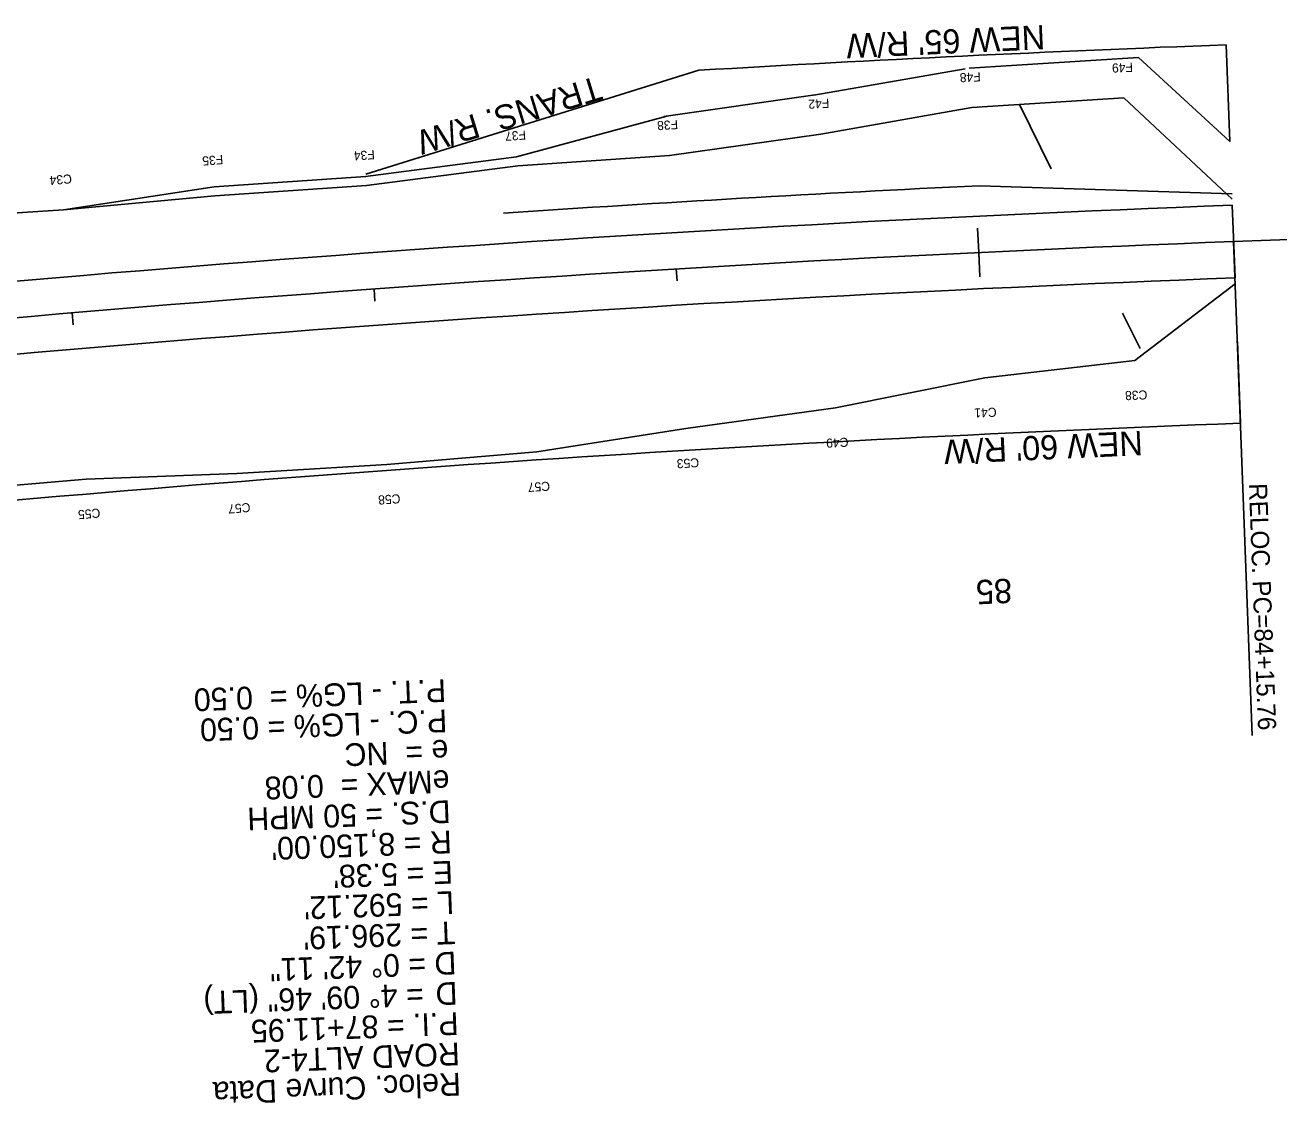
# Model space of a CAD drawing. Extents: x 1475170 to 1480100, y 1103245 to 1119475.
# Drawn here: x 1478026.2 to 1478440.1, y 1111115.9 to 1111471.6 of the extents above; entities that cross this region are included whole.
import ezdxf

# ---------------------------------------------------------------- set-up
doc = ezdxf.new("R2010")
doc.units = 0
for name, color, linetype in [('RD_HC_CL_Rel', 7, 'Continuous'), ('RD_HC_Data_Rel', 7, 'Continuous'), ('RD_HC_Data_Tic_Rel', 7, 'Continuous'), ('RD_HC_TX_Rel_Sta50', 7, 'Continuous'), ('RD_PD_CstnLmt', 7, 'Continuous'), ('RD_PD_CstnLmt_TX', 7, 'Continuous'), ('RD_PD_DR_ErosCtrl', 7, 'Continuous'), ('RD_PD_DR_Pipe', 7, 'Continuous'), ('RD_PD_Final_TrvlWay', 7, 'Continuous'), ('RD_PD_GR', 7, 'Continuous'), ('RD_PD_RW', 7, 'Continuous'), ('RD_PD_RW_TX', 7, 'Continuous')]:
    doc.layers.add(name, color=color, linetype=linetype)

msp = doc.modelspace()

# ---------------------------------------------------------------- linework, layer by layer
at = {"layer": 'RD_HC_CL_Rel'}
msp.add_line((1478857.19, 1111416.47), (1478425.19, 1111400.18), dxfattribs=at)
msp.add_arc((1478732.36, 1103255.97), 8150, 92.160003, 96.322689, dxfattribs=at)
at = {"layer": 'RD_HC_Data_Rel'}
msp.add_line((1478425.19, 1111400.18), (1478431.34, 1111237.13), dxfattribs=at)
at = {"layer": 'RD_HC_Data_Tic_Rel'}
for p, q in [((1478341.03, 1111396.57), (1478340.65, 1111404.56)), ((1478341.03, 1111396.57), (1478341.41, 1111388.58)), ((1478241.18, 1111391.15), (1478241.42, 1111387.16)), ((1478141.4, 1111384.51), (1478141.69, 1111380.52)), ((1478041.71, 1111376.65), (1478042.05, 1111372.67))]:
    msp.add_line(p, q, dxfattribs=at)
at = {"layer": 'RD_PD_CstnLmt'}
for p, q in [((1478338.73, 1111444.41), (1478288.84, 1111435.67)), ((1478288.84, 1111435.67), (1478238.91, 1111428.63)), ((1478238.91, 1111428.63), (1478188.8, 1111425.15)), ((1478188.8, 1111425.15), (1478138.91, 1111418.67)), ((1478088.82, 1111415.27), (1478038.82, 1111410.65)), ((1478138.91, 1111418.67), (1478088.82, 1111415.27)), ((1478038.82, 1111410.65), (1477988.68, 1111407.51)), ((1478343.02, 1111355.23), (1478293.74, 1111345.27)), ((1478293.74, 1111345.27), (1478244.36, 1111338.5)), ((1478244.36, 1111338.5), (1478195.09, 1111330.72)), ((1478195.09, 1111330.72), (1478145.61, 1111326.55)), ((1478145.61, 1111326.55), (1478096.04, 1111323.64)), ((1478046.37, 1111321.78), (1477996.9, 1111317.46)), ((1478096.04, 1111323.64), (1478046.37, 1111321.78))]:
    msp.add_line(p, q, dxfattribs=at)
for points in [[(1478424.66, 1111414.17), (1478388.93, 1111447.58), (1478338.73, 1111444.41)], [(1478425.72, 1111386.19), (1478392.57, 1111360.95), (1478343.02, 1111355.23)]]:
    msp.add_lwpolyline(points, dxfattribs=at)
at = {"layer": 'RD_PD_DR_ErosCtrl'}
for p, q in [((1478336.49, 1111457.21), (1478286.59, 1111448.48)), ((1478287.02, 1111448.55), (1478237.1, 1111441.5)), ((1478238.01, 1111441.6), (1478188.42, 1111428.12)), ((1478188.42, 1111428.12), (1478138.53, 1111421.64)), ((1478138.71, 1111421.66), (1478088.61, 1111418.26)), ((1478088.54, 1111418.26), (1478038.82, 1111410.65))]:
    msp.add_line(p, q, dxfattribs=at)
msp.add_lwpolyline([(1478423.94, 1111433.15), (1478393.72, 1111460.91), (1478337.91, 1111457.38)], dxfattribs=at)
at = {"layer": 'RD_PD_DR_Pipe'}
for p, q in [((1478364.96, 1111424.15), (1478354.44, 1111445.4)), ((1478394.27, 1111364.92), (1478388.54, 1111376.51))]:
    msp.add_line(p, q, dxfattribs=at)
at = {"layer": 'RD_PD_Final_TrvlWay'}
msp.add_line((1478425.64, 1111388.19), (1478424.74, 1111412.17), dxfattribs=at)
for radius in [8162, 8138]:
    msp.add_arc((1478732.36, 1103255.97), radius, 92.160003, 96.322689, dxfattribs=at)
at = {"layer": 'RD_PD_GR'}
msp.add_line((1478424.71, 1111415.96), (1478341.24, 1111418.6), dxfattribs=at)
msp.add_arc((1478732.36, 1103255.97), 8172, 92.743315, 93.846833, dxfattribs=at)
at = {"layer": 'RD_PD_RW'}
for p, q in [((1478422.74, 1111465.13), (1478423.94, 1111433.15)), ((1478248.63, 1111456.71), (1478138.64, 1111422.39)), ((1478426.43, 1111367.2), (1478427.45, 1111340.22))]:
    msp.add_line(p, q, dxfattribs=at)
for radius, end in [(8215, 93.375778), (8090, 95.564264)]:
    msp.add_arc((1478732.36, 1103255.97), radius, 92.160003, end, dxfattribs=at)

# ---------------------------------------------------------------- texts
at = {"layer": 'RD_HC_Data_Rel'}
for s, height, rotation, p in [('RELOC. PC=84+15.76', 6, 272.16, (1478430.2, 1111320.31)), ('P.T. - LG% =  0.50', 7.5, 182.16, (1478165.01, 1111255.76)), ('P.C. - LG% = 0.50', 7.5, 182.16, (1478165.38, 1111245.77)), ('e =  NC', 7.5, 182.16, (1478165.76, 1111235.77)), ('eMAX =  0.08', 7.5, 182.16, (1478166.14, 1111225.78)), ('D.S. = 50 MPH', 7.5, 182.16, (1478166.51, 1111215.79)), ("R = 8,150.00'", 7.5, 182.16, (1478166.89, 1111205.79)), ("E = 5.38'", 7.5, 182.16, (1478167.27, 1111195.8)), ("L = 592.12'", 7.5, 182.16, (1478167.64, 1111185.81)), ("T = 296.19'", 7.5, 182.16, (1478168.02, 1111175.82)), ('D = 0%%d 42\' 11"', 7.5, 182.16, (1478168.4, 1111165.82)), ('    = 4%%d 09\' 46" (LT)', 7.5, 182.16, (1478168.78, 1111155.83)), ('D', 7.5, 182.16, (1478168.78, 1111155.83)), ('P.I. = 87+11.95', 7.5, 182.16, (1478169.15, 1111145.84)), ('ROAD ALT4-2', 7.5, 182.16, (1478169.53, 1111135.84)), ('Reloc. Curve Data', 7.5, 182.16, (1478169.91, 1111125.85))]:
    msp.add_text(s, height=height, rotation=rotation, dxfattribs=at).set_placement(p)
at = {"layer": 'RD_HC_TX_Rel_Sta50'}
msp.add_text('85', height=8, rotation=182.7522, dxfattribs=at).set_placement((1478351.81, 1111288.96))
at = {"layer": 'RD_PD_CstnLmt_TX'}
for s, rotation, p in [('F49', 182.4007, (1478391.87, 1111459.21)), ('F48', 182.7522, (1478341.6, 1111456.06)), ('F42', 183.1037, (1478291.6, 1111447.34)), ('F38', 183.4552, (1478241.64, 1111440.32)), ('F37', 183.8067, (1478191.43, 1111436.85)), ('F35', 184.5097, (1478091.45, 1111428.76)), ('F34', 184.1582, (1478141.5, 1111430.39)), ('C34', 184.8612, (1478041.48, 1111422.42)), ('C38', 182.4007, (1478396.63, 1111351.11)), ('C41', 182.7522, (1478346.86, 1111345.4)), ('C49', 183.1037, (1478297.93, 1111335.49)), ('C53', 183.4552, (1478248.6, 1111328.74)), ('C57', 183.8067, (1478199.37, 1111320.98)), ('C58', 184.1582, (1478149.98, 1111316.85)), ('C55', 184.8612, (1478050.86, 1111312.12)), ('C57', 184.5097, (1478100.44, 1111313.95))]:
    msp.add_text(s, height=3, rotation=rotation, dxfattribs=at).set_placement(p)
at = {"layer": 'RD_PD_RW_TX'}
for s, rotation, p in [("NEW 65' R/W", 182.6268, (1478362.72, 1111471.66)), ('TRANS. R/W', 197.1047, (1478214.99, 1111454.92)), ("NEW 60' R/W", 182.6268, (1478394.97, 1111337.7))]:
    msp.add_text(s, height=8, rotation=rotation, dxfattribs=at).set_placement(p)

doc.saveas('drawing.dxf')
